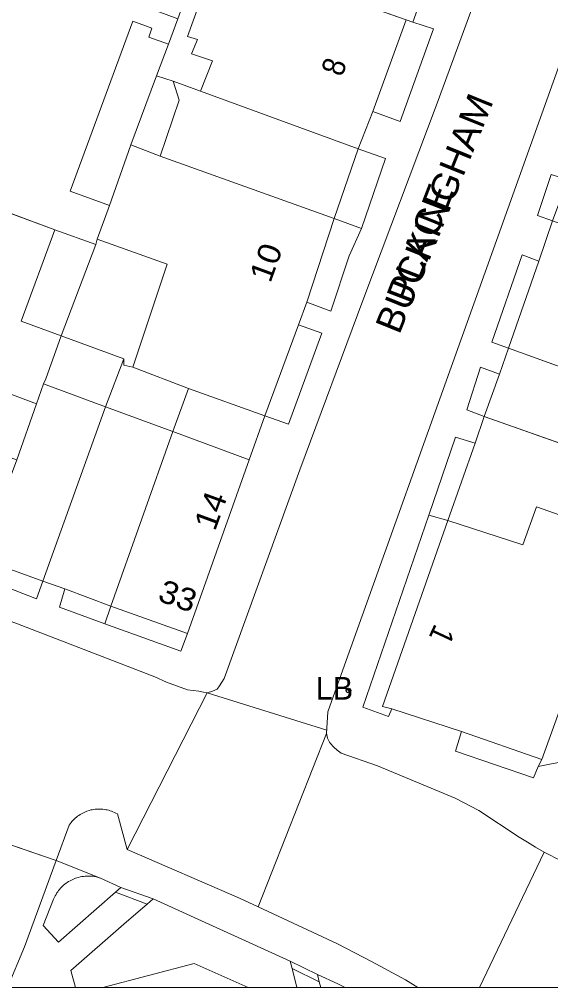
# Model space of a CAD drawing. Extents: x 528790 to 529292, y 179350 to 179856.
# Drawn here: x 529148.9 to 529183.9, y 179356 to 179419.8 of the extents above; entities that cross this region are included whole.
import ezdxf

# ---------------------------------------------------------------- set-up
doc = ezdxf.new("R2010")
doc.units = 0
doc.header["$LTSCALE"] = 0.6
doc.header["$PDMODE"] = 32
doc.header["$PDSIZE"] = 0.3
for name, color, linetype, lineweight in [('1', 7, 'Continuous', 13), ('2', 7, 'Continuous', 13), ('7', 7, 'Continuous', 13)]:
    doc.layers.add(name, color=color, linetype=linetype, lineweight=lineweight)
doc.layers.add('3', color=7, linetype='Continuous')
doc.layers.add('5', color=7, linetype='Continuous')

msp = doc.modelspace()

# ---------------------------------------------------------------- linework, layer by layer
at = {"layer": '1'}
for points in [[(529174.35, 179419.8), (529174.8, 179419.65), (529180.15, 179434.55), (529179.7, 179434.8), (529166.4, 179440.8), (529166.35, 179440.5), (529164, 179434.4), (529166.95, 179433.05), (529169.75, 179431.8), (529169, 179429.8), (529171.75, 179428.55), (529170.4, 179424.8), (529169.25, 179421.6)], [(529154, 179405.35), (529154.8, 179407.55), (529152.2, 179408.5), (529156.35, 179419.7), (529157.6, 179419.25), (529157.4, 179418.65), (529158.7, 179418.2), (529159.3, 179419.85), (529145.6, 179424.95), (529144.8, 179422.75), (529144.15, 179421), (529142.4, 179416.4), (529143.2, 179416.1), (529140.9, 179409.8), (529151.2, 179405.95), (529153.9, 179405)], [(529158.7, 179418.2), (529157.9, 179416.1), (529159, 179415.75), (529160.8, 179415.1), (529161.6, 179417.1), (529160.2, 179417.55), (529160.6, 179418.5), (529159.95, 179418.7), (529161.25, 179422.3), (529163.25, 179421.65), (529163.95, 179423.5), (529161, 179424.45), (529159.9, 179421.5), (529159.3, 179419.85)], [(529172.15, 179413.75), (529174.35, 179419.8), (529169.25, 179421.6), (529163.95, 179423.5), (529163.25, 179421.65), (529161.25, 179422.3), (529159.95, 179418.7), (529160.6, 179418.5), (529160.2, 179417.55), (529161.6, 179417.1), (529160.8, 179415.1), (529171.2, 179411.3)], [(529156.2, 179411.55), (529157.9, 179416.1), (529158.7, 179418.2), (529157.4, 179418.65), (529157.6, 179419.25), (529156.35, 179419.7), (529152.2, 179408.5), (529154.8, 179407.55)], [(529172.15, 179413.75), (529173.95, 179413.1), (529176.15, 179419.2), (529174.8, 179419.65), (529174.35, 179419.8)], [(529158.15, 179410.8), (529159.4, 179414.5), (529159, 179415.75), (529157.9, 179416.1), (529156.2, 179411.55)], [(529159, 179415.75), (529159.4, 179414.5), (529158.15, 179410.8), (529169.6, 179406.7), (529171.2, 179411.3), (529160.8, 179415.1)], [(529167.25, 179399.7), (529167.8, 179401.2), (529169.6, 179406.7), (529158.15, 179410.8), (529156.2, 179411.55), (529154.8, 179407.55), (529154, 179405.35), (529158.6, 179403.7), (529156.35, 179396.9), (529160, 179395.5), (529165.05, 179393.7)], [(529171.4, 179406.05), (529173, 179410.65), (529171.2, 179411.3), (529169.6, 179406.7)], [(529150, 179394.5), (529150.45, 179395.8), (529150.6, 179396.15), (529151.613, 179398.966), (529148.989, 179399.93), (529151.2, 179405.95), (529140.9, 179409.8), (529138.55, 179403.45), (529137.8, 179403.7), (529136.35, 179399.6), (529137.75, 179399.05), (529140.95, 179397.85), (529143.4, 179396.9), (529145.35, 179396.2), (529147.7, 179395.35)], [(529185, 179409.25), (529183.9, 179409.6), (529183, 179406.9), (529184, 179406.55)], [(529170.6, 179404.25), (529171.4, 179406.05), (529169.6, 179406.7), (529167.8, 179401.2), (529169.4, 179400.6)], [(529192.05, 179394.2), (529194.427, 179400.927), (529195.55, 179400.501), (529198.45, 179399.4), (529199.2, 179401), (529196.05, 179402.15), (529195, 179402.55), (529184, 179406.55), (529183.1, 179403.9), (529181.1, 179398.15)], [(529153.9, 179405), (529151.2, 179405.95), (529148.989, 179399.93), (529151.613, 179398.966)], [(529158.6, 179403.7), (529154, 179405.35), (529153.9, 179405), (529151.613, 179398.966), (529155.75, 179397.45), (529155.75, 179397.05), (529156.35, 179396.9)], [(529183.1, 179403.9), (529182, 179404.3), (529180, 179398.55), (529181.1, 179398.15)], [(529165.05, 179393.7), (529166.6, 179393.15), (529168.8, 179399.15), (529167.25, 179399.7)], [(529155.75, 179397.45), (529151.613, 179398.966), (529150.6, 179396.15), (529150.45, 179395.8), (529154.55, 179394.3)], [(529194.322, 179390.628), (529195.5, 179392.9), (529192.05, 179394.2), (529181.1, 179398.15), (529180.5, 179396.45), (529179.5, 179393.65), (529189, 179390.3), (529193.4, 179388.85)], [(529155.75, 179397.45), (529154.55, 179394.3), (529158.9, 179392.7), (529158.97, 179392.67), (529160, 179395.5), (529156.35, 179396.9), (529155.75, 179397.05)], [(529180.5, 179396.45), (529179.25, 179396.9), (529178.35, 179394.1), (529179.5, 179393.65)], [(529154.55, 179394.3), (529150.45, 179395.8), (529150, 179394.5), (529148.7, 179390.8), (529146.25, 179384.3), (529147.55, 179383.85), (529150.4, 179382.8)], [(529160, 179395.5), (529158.97, 179392.67), (529164, 179390.8), (529165.05, 179393.7)], [(529148.7, 179390.8), (529150, 179394.5), (529147.7, 179395.35), (529146.4, 179391.6)], [(529150.4, 179382.8), (529151.85, 179382.3), (529154.9, 179381.15), (529158.97, 179392.67), (529158.9, 179392.7), (529154.55, 179394.3)], [(529189.51, 179388.389), (529188.452, 179388.767), (529189, 179390.3), (529179.5, 179393.65), (529178.9, 179391.9), (529177.1, 179386.8), (529182.05, 179385.2), (529182.95, 179387.7), (529187.5, 179386.1), (529188.55, 179385.7)], [(529164, 179390.8), (529158.97, 179392.67), (529154.9, 179381.15), (529159.95, 179379.35)], [(529177.1, 179386.8), (529178.9, 179391.9), (529177.6, 179392.3), (529175.85, 179387.15)], [(529175.85, 179387.15), (529171.5, 179374.5), (529173.2, 179373.9), (529173.4, 179374.4), (529172.8, 179374.55), (529177.1, 179386.8)], [(529187.4, 179382.55), (529188.55, 179385.7), (529187.5, 179386.1), (529182.95, 179387.7), (529182.05, 179385.2), (529177.1, 179386.8), (529172.8, 179374.55), (529173.4, 179374.4), (529178, 179372.9), (529183.3, 179371.05), (529185.2, 179376.35), (529186.75, 179380.7)], [(529147.55, 179383.85), (529147.15, 179382.75), (529150, 179381.65), (529150.4, 179382.8)], [(529154.9, 179381.15), (529151.85, 179382.3), (529151.5, 179381.1), (529154.5, 179380)], [(529186.75, 179380.7), (529188.35, 179378.7), (529185.2, 179376.35), (529183.3, 179371.05), (529183.05, 179370.6), (529189.15, 179371.8), (529193, 179374.5), (529187.8, 179382.1), (529187.4, 179382.55)], [(529154.5, 179380), (529159.5, 179378.2), (529159.95, 179379.35), (529154.9, 179381.15)], [(529169.113, 179372.761), (529169.11, 179372.816), (529169.109, 179372.871), (529169.111, 179372.926), (529169.115, 179372.981), (529161.25, 179375.45), (529155.96, 179365.12), (529163.36, 179361.91), (529164.59, 179361.34)], [(529175.133, 179356.024), (529179.179, 179356.024), (529183.458, 179364.958), (529182.879, 179365.274), (529182.342, 179365.603), (529181.808, 179365.935), (529179.15, 179367.688), (529177.592, 179368.518), (529172.467, 179370.634), (529170.078, 179371.478), (529169.972, 179371.548), (529169.889, 179371.607), (529169.808, 179371.671), (529169.73, 179371.737), (529169.655, 179371.807), (529169.576, 179371.884), (529169.504, 179371.958), (529169.434, 179372.034), (529169.368, 179372.113), (529169.308, 179372.196), (529169.254, 179372.282), (529169.208, 179372.372), (529169.171, 179372.467), (529169.167, 179372.482), (529169.149, 179372.543), (529169.137, 179372.597), (529169.127, 179372.651), (529169.119, 179372.706), (529169.113, 179372.761), (529164.59, 179361.34), (529169.82, 179358.91), (529172.07, 179357.74), (529174.3, 179356.53)], [(529178, 179372.9), (529177.6, 179371.6), (529182.75, 179369.85), (529183.05, 179370.6), (529183.3, 179371.05)], [(529170.331, 179356.024), (529175.133, 179356.024), (529174.3, 179356.53), (529172.07, 179357.74), (529169.82, 179358.91), (529164.59, 179361.34), (529163.36, 179361.91), (529155.96, 179365.12), (529155.32, 179367.47), (529155.22, 179367.53), (529155.13, 179367.57), (529155.03, 179367.61), (529154.94, 179367.65), (529154.85, 179367.68), (529154.75, 179367.71), (529154.65, 179367.73), (529154.56, 179367.75), (529154.46, 179367.77), (529154.36, 179367.78), (529154.26, 179367.79), (529154.16, 179367.79), (529154.06, 179367.79), (529153.96, 179367.78), (529153.86, 179367.78), (529153.76, 179367.76), (529153.66, 179367.75), (529153.57, 179367.73), (529153.47, 179367.7), (529153.31, 179367.65), (529153.22, 179367.61), (529153.13, 179367.57), (529153.04, 179367.53), (529152.95, 179367.48), (529152.86, 179367.43), (529152.78, 179367.37), (529152.7, 179367.32), (529152.62, 179367.25), (529152.54, 179367.19), (529152.47, 179367.12), (529152.4, 179367.05), (529152.33, 179366.98), (529152.27, 179366.9), (529152.21, 179366.82), (529152.15, 179366.74), (529151.29, 179364.41), (529154.22, 179363.24), (529155.55, 179362.63), (529157.68, 179361.88), (529166.72, 179357.77), (529168.51, 179356.89), (529169.85, 179356.28)], [(529148.072, 179356.024), (529149.2, 179358.71), (529151.29, 179364.41), (529144.68, 179366.66), (529139.93, 179357.02), (529140.071, 179356.024)], [(529148.072, 179356.024), (529152.566, 179356.024), (529152.25, 179357.16), (529155.75, 179360.2), (529157.15, 179361.42), (529157.28, 179361.53), (529155.19, 179362.31), (529151.44, 179359.02), (529150.43, 179360.12), (529151.12, 179361.85), (529151.18, 179361.99), (529151.23, 179362.08), (529151.28, 179362.17), (529151.33, 179362.26), (529151.39, 179362.34), (529151.45, 179362.42), (529151.51, 179362.5), (529151.58, 179362.58), (529151.7, 179362.71), (529151.78, 179362.77), (529151.86, 179362.84), (529151.94, 179362.9), (529152.02, 179362.96), (529152.11, 179363.01), (529152.2, 179363.06), (529152.29, 179363.11), (529152.38, 179363.15), (529152.47, 179363.19), (529152.57, 179363.23), (529152.66, 179363.26), (529152.76, 179363.29), (529152.88, 179363.32), (529152.98, 179363.34), (529153.08, 179363.35), (529153.19, 179363.37), (529153.29, 179363.37), (529153.4, 179363.37), (529153.5, 179363.37), (529153.61, 179363.37), (529153.71, 179363.36), (529153.81, 179363.34), (529153.92, 179363.32), (529154.02, 179363.3), (529154.12, 179363.27), (529154.22, 179363.24), (529151.29, 179364.41), (529149.2, 179358.71)], [(529154.22, 179363.24), (529154.12, 179363.27), (529154.02, 179363.3), (529153.92, 179363.32), (529153.81, 179363.34), (529153.71, 179363.36), (529153.61, 179363.37), (529153.5, 179363.37), (529153.4, 179363.37), (529153.29, 179363.37), (529153.19, 179363.37), (529153.08, 179363.35), (529152.98, 179363.34), (529152.88, 179363.32), (529152.76, 179363.29), (529152.66, 179363.26), (529152.57, 179363.23), (529152.47, 179363.19), (529152.38, 179363.15), (529152.29, 179363.11), (529152.2, 179363.06), (529152.11, 179363.01), (529152.02, 179362.96), (529151.94, 179362.9), (529151.86, 179362.84), (529151.78, 179362.77), (529151.7, 179362.71), (529151.58, 179362.58), (529151.51, 179362.5), (529151.45, 179362.42), (529151.39, 179362.34), (529151.33, 179362.26), (529151.28, 179362.17), (529151.23, 179362.08), (529151.18, 179361.99), (529151.12, 179361.85), (529150.43, 179360.12), (529151.44, 179359.02), (529155.19, 179362.31), (529155.55, 179362.63)], [(529157.28, 179361.53), (529157.68, 179361.88), (529155.55, 179362.63), (529155.19, 179362.31)], [(529152.566, 179356.024), (529154.372, 179356.024), (529160.38, 179357.61), (529163.942, 179356.024), (529167.156, 179356.024), (529166.86, 179357.2), (529166.84, 179357.28), (529166.72, 179357.77), (529157.68, 179361.88), (529157.28, 179361.53), (529157.15, 179361.42), (529155.75, 179360.2), (529152.25, 179357.16)], [(529166.72, 179357.77), (529166.84, 179357.28), (529168.63, 179356.41), (529168.51, 179356.89)], [(529163.942, 179356.024), (529160.38, 179357.61), (529154.372, 179356.024)], [(529168.73, 179356.024), (529168.63, 179356.41), (529166.84, 179357.28), (529166.86, 179357.2), (529167.156, 179356.024)], [(529170.331, 179356.024), (529169.85, 179356.28), (529168.51, 179356.89), (529168.63, 179356.41), (529168.73, 179356.024)]]:
    msp.add_lwpolyline(points, close=True, dxfattribs=at)
for points in [[(529180.15, 179434.55), (529174.8, 179419.65), (529176.15, 179419.2), (529173.95, 179413.1), (529172.15, 179413.75), (529171.2, 179411.3), (529173, 179410.65), (529171.4, 179406.05), (529170.6, 179404.25), (529169.4, 179400.6), (529167.8, 179401.2), (529167.25, 179399.7), (529168.8, 179399.15), (529166.6, 179393.15), (529165.05, 179393.7), (529164, 179390.8), (529159.95, 179379.35), (529159.5, 179378.2), (529154.5, 179380), (529151.5, 179381.1), (529151.85, 179382.3), (529150.4, 179382.8), (529150, 179381.65), (529147.15, 179382.75)], [(529181.6, 179428.5), (529176.4, 179414.3), (529171.5, 179401.3), (529167.35, 179390.15), (529162.35, 179376.4), (529162.05, 179375.9), (529161.9, 179375.7), (529161.6, 179375.55), (529161.25, 179375.45), (529169.115, 179372.981), (529169.121, 179373.036), (529169.129, 179373.091), (529169.131, 179373.129), (529169.2, 179374.196), (529169.204, 179374.262), (529169.205, 179374.273), (529189.9, 179432.1)], [(529189.9, 179432.1), (529169.205, 179374.273), (529169.204, 179374.262), (529169.2, 179374.196), (529169.131, 179373.129), (529169.129, 179373.091), (529169.121, 179373.036), (529169.115, 179372.981), (529169.111, 179372.926), (529169.109, 179372.871), (529169.11, 179372.816), (529169.113, 179372.761), (529169.119, 179372.706), (529169.127, 179372.651), (529169.137, 179372.597), (529169.149, 179372.543), (529169.167, 179372.482), (529169.171, 179372.467), (529169.208, 179372.372), (529169.254, 179372.282), (529169.308, 179372.196), (529169.368, 179372.113), (529169.434, 179372.034), (529169.504, 179371.958), (529169.576, 179371.884), (529169.655, 179371.807), (529169.73, 179371.737), (529169.808, 179371.671), (529169.889, 179371.607), (529169.972, 179371.548), (529170.078, 179371.478), (529172.467, 179370.634), (529177.592, 179368.518), (529179.15, 179367.688), (529181.808, 179365.935), (529182.342, 179365.603), (529182.879, 179365.274), (529183.458, 179364.958), (529183.932, 179364.699)], [(529148.75, 179380), (529157.8, 179376.5), (529158.55, 179376.15), (529159.95, 179375.65), (529160.7, 179375.55), (529161, 179375.5), (529161.25, 179375.45), (529161.6, 179375.55), (529161.9, 179375.7), (529162.05, 179375.9), (529162.35, 179376.4), (529167.35, 179390.15), (529171.5, 179401.3), (529176.4, 179414.3), (529181.6, 179428.5)], [(529189.15, 179371.8), (529183.05, 179370.6), (529182.75, 179369.85), (529177.6, 179371.6), (529178, 179372.9), (529173.4, 179374.4), (529173.2, 179373.9), (529171.5, 179374.5), (529175.85, 179387.15), (529177.6, 179392.3), (529178.9, 179391.9), (529179.5, 179393.65), (529178.35, 179394.1), (529179.25, 179396.9), (529180.5, 179396.45), (529181.1, 179398.15), (529180, 179398.55), (529182, 179404.3), (529183.1, 179403.9), (529184, 179406.55), (529183, 179406.9), (529183.9, 179409.6)], [(529144.68, 179366.66), (529151.29, 179364.41), (529152.15, 179366.74), (529152.21, 179366.82), (529152.27, 179366.9), (529152.33, 179366.98), (529152.4, 179367.05), (529152.47, 179367.12), (529152.54, 179367.19), (529152.62, 179367.25), (529152.7, 179367.32), (529152.78, 179367.37), (529152.86, 179367.43), (529152.95, 179367.48), (529153.04, 179367.53), (529153.13, 179367.57), (529153.22, 179367.61), (529153.31, 179367.65), (529153.47, 179367.7), (529153.57, 179367.73), (529153.66, 179367.75), (529153.76, 179367.76), (529153.86, 179367.78), (529153.96, 179367.78), (529154.06, 179367.79), (529154.16, 179367.79), (529154.26, 179367.79), (529154.36, 179367.78), (529154.46, 179367.77), (529154.56, 179367.75), (529154.65, 179367.73), (529154.75, 179367.71), (529154.85, 179367.68), (529154.94, 179367.65), (529155.03, 179367.61), (529155.13, 179367.57), (529155.22, 179367.53), (529155.32, 179367.47), (529155.96, 179365.12), (529161.25, 179375.45), (529161, 179375.5), (529160.7, 179375.55), (529159.95, 179375.65), (529158.55, 179376.15), (529157.8, 179376.5), (529148.75, 179380)], [(529183.932, 179364.699), (529183.458, 179364.958), (529179.179, 179356.024), (529189.094, 179356.024)]]:
    msp.add_lwpolyline(points, dxfattribs=at)
at = {"layer": '2'}
for p, q in [((529174.35, 179419.8), (529169.25, 179421.6)), ((529159.3, 179419.85), (529158.7, 179418.2)), ((529172.15, 179413.75), (529174.35, 179419.8)), ((529174.8, 179419.65), (529174.35, 179419.8)), ((529158.7, 179418.2), (529157.9, 179416.1)), ((529157.9, 179416.1), (529156.2, 179411.55)), ((529157.9, 179416.1), (529159, 179415.75)), ((529160.8, 179415.1), (529159, 179415.75)), ((529160.8, 179415.1), (529171.2, 179411.3)), ((529171.2, 179411.3), (529172.15, 179413.75)), ((529156.2, 179411.55), (529154.8, 179407.55)), ((529158.15, 179410.8), (529156.2, 179411.55)), ((529169.6, 179406.7), (529158.15, 179410.8)), ((529169.6, 179406.7), (529171.2, 179411.3)), ((529140.9, 179409.8), (529151.2, 179405.95)), ((529154.8, 179407.55), (529154, 179405.35)), ((529169.6, 179406.7), (529167.8, 179401.2)), ((529171.4, 179406.05), (529169.6, 179406.7)), ((529184, 179406.55), (529183.1, 179403.9)), ((529153.9, 179405), (529151.2, 179405.95)), ((529151.613, 179398.966), (529153.9, 179405)), ((529154, 179405.35), (529153.9, 179405)), ((529183.1, 179403.9), (529181.1, 179398.15)), ((529167.8, 179401.2), (529167.25, 179399.7)), ((529167.25, 179399.7), (529165.05, 179393.7)), ((529151.613, 179398.966), (529155.75, 179397.45)), ((529181.1, 179398.15), (529180.5, 179396.45)), ((529181.1, 179398.15), (529192.05, 179394.2)), ((529154.55, 179394.3), (529155.75, 179397.45)), ((529160, 179395.5), (529156.35, 179396.9)), ((529180.5, 179396.45), (529179.5, 179393.65)), ((529150.45, 179395.8), (529150, 179394.5)), ((529150.45, 179395.8), (529154.55, 179394.3)), ((529158.97, 179392.67), (529160, 179395.5)), ((529165.05, 179393.7), (529160, 179395.5)), ((529147.7, 179395.35), (529150, 179394.5)), ((529150, 179394.5), (529148.7, 179390.8)), ((529154.55, 179394.3), (529150.4, 179382.8)), ((529165.05, 179393.7), (529164, 179390.8)), ((529179.5, 179393.65), (529178.9, 179391.9)), ((529179.5, 179393.65), (529189, 179390.3)), ((529154.9, 179381.15), (529158.97, 179392.67)), ((529158.97, 179392.67), (529164, 179390.8)), ((529178.9, 179391.9), (529177.1, 179386.8)), ((529164, 179390.8), (529159.95, 179379.35)), ((529175.85, 179387.15), (529177.1, 179386.8)), ((529150.4, 179382.8), (529147.55, 179383.85)), ((529151.85, 179382.3), (529150.4, 179382.8)), ((529154.9, 179381.15), (529151.85, 179382.3)), ((529154.5, 179380), (529154.9, 179381.15)), ((529159.95, 179379.35), (529154.9, 179381.15)), ((529185.2, 179376.35), (529183.3, 179371.05)), ((529161.25, 179375.45), (529155.96, 179365.12)), ((529161.25, 179375.45), (529169.115, 179372.981)), ((529173.4, 179374.4), (529178, 179372.9)), ((529169.113, 179372.761), (529164.59, 179361.34)), ((529178, 179372.9), (529183.3, 179371.05)), ((529183.3, 179371.05), (529183.05, 179370.6)), ((529151.29, 179364.41), (529144.68, 179366.66)), ((529179.179, 179356.024), (529183.458, 179364.958)), ((529151.29, 179364.41), (529149.2, 179358.71)), ((529154.22, 179363.24), (529151.29, 179364.41)), ((529155.55, 179362.63), (529154.22, 179363.24)), ((529155.19, 179362.31), (529155.55, 179362.63)), ((529157.28, 179361.53), (529155.19, 179362.31)), ((529155.55, 179362.63), (529157.68, 179361.88)), ((529157.68, 179361.88), (529157.28, 179361.53)), ((529166.72, 179357.77), (529157.68, 179361.88)), ((529148.072, 179356.024), (529149.2, 179358.71)), ((529166.72, 179357.77), (529168.51, 179356.89)), ((529166.84, 179357.28), (529166.72, 179357.77)), ((529166.84, 179357.28), (529168.63, 179356.41)), ((529168.63, 179356.41), (529168.51, 179356.89)), ((529168.73, 179356.024), (529168.63, 179356.41))]:
    msp.add_line(p, q, dxfattribs=at)
for points in [[(529161.25, 179375.45), (529161.6, 179375.55), (529161.9, 179375.7), (529162.05, 179375.9), (529162.35, 179376.4), (529167.35, 179390.15), (529171.5, 179401.3), (529176.4, 179414.3), (529181.6, 179428.5), (529182.15, 179429.7), (529182.7, 179430.8), (529183.15, 179432.05), (529183.5, 179433.3), (529183.7, 179434), (529183.75, 179434.4), (529183.75, 179434.75), (529183.6, 179435.15), (529183.5, 179435.55)], [(529179.7, 179434.8), (529180.15, 179434.55), (529174.8, 179419.65)], [(529190.2, 179432.45), (529189.9, 179432.1), (529169.205, 179374.273), (529169.204, 179374.262), (529169.2, 179374.196), (529169.131, 179373.129), (529169.129, 179373.091), (529169.121, 179373.036), (529169.115, 179372.981)], [(529163.95, 179423.5), (529163.25, 179421.65), (529161.25, 179422.3), (529159.95, 179418.7), (529160.6, 179418.5), (529160.2, 179417.55), (529161.6, 179417.1), (529160.8, 179415.1)], [(529158.7, 179418.2), (529157.4, 179418.65), (529157.6, 179419.25), (529156.35, 179419.7), (529152.2, 179408.5), (529154.8, 179407.55)], [(529174.8, 179419.65), (529176.15, 179419.2), (529173.95, 179413.1), (529172.15, 179413.75)], [(529159, 179415.75), (529159.4, 179414.5), (529158.15, 179410.8)], [(529171.4, 179406.05), (529173, 179410.65), (529171.2, 179411.3)], [(529184, 179406.55), (529183, 179406.9), (529183.9, 179409.6), (529185, 179409.25)], [(529151.2, 179405.95), (529148.989, 179399.93), (529151.613, 179398.966)], [(529171.4, 179406.05), (529170.6, 179404.25), (529169.4, 179400.6), (529167.8, 179401.2)], [(529156.35, 179396.9), (529158.6, 179403.7), (529154, 179405.35)], [(529183.1, 179403.9), (529182, 179404.3), (529180, 179398.55), (529181.1, 179398.15)], [(529165.05, 179393.7), (529166.6, 179393.15), (529168.8, 179399.15), (529167.25, 179399.7)], [(529151.613, 179398.966), (529150.6, 179396.15), (529150.45, 179395.8)], [(529155.75, 179397.45), (529155.75, 179397.05), (529156.35, 179396.9)], [(529180.5, 179396.45), (529179.25, 179396.9), (529178.35, 179394.1), (529179.5, 179393.65)], [(529154.55, 179394.3), (529158.9, 179392.7), (529158.97, 179392.67)], [(529175.85, 179387.15), (529177.6, 179392.3), (529178.9, 179391.9)], [(529129.75, 179387.2), (529130, 179386.85), (529130.4, 179386.6), (529131.6, 179386.1), (529139.9, 179383.2), (529148.75, 179380), (529157.8, 179376.5), (529158.55, 179376.15), (529159.95, 179375.65), (529160.7, 179375.55), (529161, 179375.5), (529161.25, 179375.45)], [(529175.85, 179387.15), (529171.5, 179374.5), (529173.2, 179373.9), (529173.4, 179374.4)], [(529177.1, 179386.8), (529182.05, 179385.2), (529182.95, 179387.7), (529187.5, 179386.1), (529188.55, 179385.7)], [(529177.1, 179386.8), (529172.8, 179374.55), (529173.4, 179374.4)], [(529147.55, 179383.85), (529147.15, 179382.75), (529150, 179381.65), (529150.4, 179382.8)], [(529154.5, 179380), (529151.5, 179381.1), (529151.85, 179382.3)], [(529159.95, 179379.35), (529159.5, 179378.2), (529154.5, 179380)], [(529193, 179374.5), (529189.15, 179371.8), (529183.05, 179370.6)], [(529169.115, 179372.981), (529169.111, 179372.926), (529169.109, 179372.871), (529169.11, 179372.816), (529169.113, 179372.761)], [(529169.113, 179372.761), (529169.119, 179372.706), (529169.127, 179372.651), (529169.137, 179372.597), (529169.149, 179372.543), (529169.167, 179372.482), (529169.171, 179372.467), (529169.208, 179372.372), (529169.254, 179372.282), (529169.308, 179372.196), (529169.368, 179372.113), (529169.434, 179372.034), (529169.504, 179371.958), (529169.576, 179371.884), (529169.655, 179371.807), (529169.73, 179371.737), (529169.808, 179371.671), (529169.889, 179371.607), (529169.972, 179371.548), (529170.078, 179371.478), (529172.467, 179370.634), (529177.592, 179368.518), (529179.15, 179367.688), (529181.808, 179365.935), (529182.342, 179365.603), (529182.879, 179365.274), (529183.458, 179364.958)], [(529183.05, 179370.6), (529182.75, 179369.85), (529177.6, 179371.6), (529178, 179372.9)], [(529151.29, 179364.41), (529152.15, 179366.74), (529152.21, 179366.82), (529152.27, 179366.9), (529152.33, 179366.98), (529152.4, 179367.05), (529152.47, 179367.12), (529152.54, 179367.19), (529152.62, 179367.25), (529152.7, 179367.32), (529152.78, 179367.37), (529152.86, 179367.43), (529152.95, 179367.48), (529153.04, 179367.53), (529153.13, 179367.57), (529153.22, 179367.61), (529153.31, 179367.65), (529153.47, 179367.7), (529153.57, 179367.73), (529153.66, 179367.75), (529153.76, 179367.76), (529153.86, 179367.78), (529153.96, 179367.78), (529154.06, 179367.79), (529154.16, 179367.79), (529154.26, 179367.79), (529154.36, 179367.78), (529154.46, 179367.77), (529154.56, 179367.75), (529154.65, 179367.73), (529154.75, 179367.71), (529154.85, 179367.68), (529154.94, 179367.65), (529155.03, 179367.61), (529155.13, 179367.57), (529155.22, 179367.53), (529155.32, 179367.47), (529155.96, 179365.12)], [(529155.96, 179365.12), (529163.36, 179361.91), (529164.59, 179361.34)], [(529183.458, 179364.958), (529183.932, 179364.699), (529184.095, 179364.619), (529184.258, 179364.538), (529184.42, 179364.457), (529184.584, 179364.378), (529184.748, 179364.302), (529184.914, 179364.23), (529185.082, 179364.166), (529185.253, 179364.109), (529185.533, 179364.039), (529185.705, 179364.009), (529185.879, 179363.986), (529186.053, 179363.97), (529186.228, 179363.96), (529186.403, 179363.958), (529186.578, 179363.963), (529186.752, 179363.975), (529186.926, 179363.994), (529187.144, 179364.029), (529187.611, 179364.159), (529188.058, 179364.351), (529188.837, 179364.767)], [(529154.22, 179363.24), (529154.12, 179363.27), (529154.02, 179363.3), (529153.92, 179363.32), (529153.81, 179363.34), (529153.71, 179363.36), (529153.61, 179363.37), (529153.5, 179363.37), (529153.4, 179363.37), (529153.29, 179363.37), (529153.19, 179363.37), (529153.08, 179363.35), (529152.98, 179363.34), (529152.88, 179363.32), (529152.76, 179363.29), (529152.66, 179363.26), (529152.57, 179363.23), (529152.47, 179363.19), (529152.38, 179363.15), (529152.29, 179363.11), (529152.2, 179363.06), (529152.11, 179363.01), (529152.02, 179362.96), (529151.94, 179362.9), (529151.86, 179362.84), (529151.78, 179362.77), (529151.7, 179362.71), (529151.58, 179362.58), (529151.51, 179362.5), (529151.45, 179362.42), (529151.39, 179362.34), (529151.33, 179362.26), (529151.28, 179362.17), (529151.23, 179362.08), (529151.18, 179361.99), (529151.12, 179361.85), (529150.43, 179360.12), (529151.44, 179359.02), (529155.19, 179362.31)], [(529157.28, 179361.53), (529157.15, 179361.42), (529155.75, 179360.2), (529152.25, 179357.16), (529152.566, 179356.024)], [(529164.59, 179361.34), (529169.82, 179358.91), (529172.07, 179357.74), (529174.3, 179356.53), (529175.133, 179356.024)], [(529154.372, 179356.024), (529160.38, 179357.61), (529163.942, 179356.024)], [(529167.156, 179356.024), (529166.86, 179357.2), (529166.84, 179357.28)], [(529168.51, 179356.89), (529169.85, 179356.28), (529170.331, 179356.024)]]:
    msp.add_lwpolyline(points, dxfattribs=at)
at = {"layer": '3'}
msp.add_point((529170.55, 179375.6), dxfattribs=at)
at = {"layer": '7'}
msp.add_lwpolyline([(528790.22, 179356.024), (529290.22, 179356.024), (529290.22, 179856.024), (528790.22, 179856.024)], close=True, dxfattribs=at)

# ---------------------------------------------------------------- texts
at = {"layer": '5'}
for s, height, rotation, width, p in [('8', 1.5, 72, 0.9, (529170.15, 179416)), ('BUCKINGHAM', 1.75, 68, 1.05, (529173.9, 179399)), ('PLACE', 1.75, 69, 1.05, (529174.65, 179401)), ('10', 1.5, 70, 1.1, (529165.4, 179402.4)), ('14', 1.5, 70, 1.1, (529161.75, 179386.05)), ('33', 1.5, 340, 1.1, (529157.9, 179381.55)), ('1', 1.5, 245, 0.9, (529176.25, 179380.05))]:
    msp.add_text(s, height=height, rotation=rotation, dxfattribs=dict(at, width=width)).set_placement(p)
msp.add_text('LB', height=1.5, dxfattribs=at).set_placement((529168.4, 179375))

doc.saveas('drawing.dxf')
